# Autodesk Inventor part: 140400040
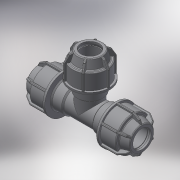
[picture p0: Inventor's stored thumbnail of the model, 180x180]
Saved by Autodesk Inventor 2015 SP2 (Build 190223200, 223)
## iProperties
Created: 2017-08
Part Number: 140400040
Material: Generic
Description: PLASSON L.14 TEE (SILVER) 40-40-40
Document SubType Name: Modeling
Designer: KIM
Density: 1 g/cm^3
Appearance: Default
Author: KIM
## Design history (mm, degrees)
derived "140400.ipt"
feature "Solid1::140400.ipt"
tag "TaggingFeature1"
body "Solid1"
other parameters: "d2" = 62, "d4" = 15 deg, "d5" = 40.92, "d6" = 13.5036, "d10" = 73, "d16" = 40.8, "d17" = 3.1, "d22" = 56, "d24" = 3.1, "d25" = 65.7, "d26" = 54.75, "d27" = 3.1, "d28" = 135 deg, "d29" = 1.86, "d31" = 2, "d46" = 150 deg, "d49" = 3.65, "d50" = 0, "d58" = 1.2, "d61" = 360 deg, "d63" = 36, "d64" = 86.5, "d78" = 180 deg, "d80" = 50.4, "d81" = 2.8, "d84" = 6.2, "d86" = 0, "d88" = 0, "d90" = 0, "d92" = 180 deg, "G_" = 18.631, "E_" = 73, "H_" = 173, "l_" = 62, "l_2" = 19
